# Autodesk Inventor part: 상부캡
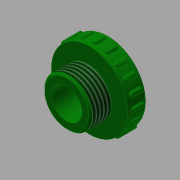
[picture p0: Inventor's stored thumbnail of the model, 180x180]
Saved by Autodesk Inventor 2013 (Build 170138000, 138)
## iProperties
Created: 2015-12
Part Number: 상부캡
Material: PC/ABS 플라스틱
Document SubType Name: Modeling
Designer: mduedu
Density: 7.86 g/cm^3
Author: mduedu
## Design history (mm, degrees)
sketch "스케치1"
  geometry: C1 r 12.5 at (0, 0); C2 r 8 at (0, 0); 1 further point
  constraints: 2 centre point, 2 coincident
  dimensions: "d1" = 25 diameter of C1; "d3" = 16 diameter of C2
extrude "돌출1" new body sketch "스케치1" distance "d4" = 12; taper "d6" = 0 deg; dims "d5" = 12, "d7" = 0
sketch "스케치2"
  geometry: C1 r 20 at (0, 0); C2 r 12.5 at (0, 0) reference; 1 further point
  constraints: 1 centre point, 1 coincident
  dimensions: "d8" = 40 diameter of C1
extrude "돌출2" join sketch "스케치2" distance "d10" = 10; taper "d11" = 0 deg
extrude "돌출3" cut sketch "스케치1" stored distance "d34" = 10; taper "d35" = 0 deg
sketch "스케치5"
  geometry: L1 (-20, 0)-(-20, 10) reference; L2 (-20, 10)-(-12.5, 10) reference; L3 (-12.5, 10)-(-12.5, 12) reference; L4 (-12.5, 12)-(12.5, 12) reference; L5 (12.5, 12)-(12.5, 10) reference; L6 (12.5, 10)-(20, 10) reference; L7 (20, 10)-(20, 0) reference; L8 (20, 0)-(12.5, 0) reference; L9 (12.5, 0)-(12.5, -12) reference; L10 (12.5, -12)-(8, -12) reference; L11 (8, -12)-(8, 0) reference; L12 (8, 0)-(-8, 0) reference; L13 (-8, 0)-(-8, -12) reference; L14 (-8, -12)-(-12.5, -12) reference; L15 (-12.5, -12)-(-12.5, 0) reference; L16 (-12.5, 0)-(-20, 0) reference; L17 (12.5, 0)-(10.5, 0); L18 (10.5, 0)-(10.5, -1); L19 (10.5, -1)-(12.5, -1); L20 (12.5, -1)-(12.5, 0); 2 further points
  constraints: 8 end point, 2 parallel, 1 horizontal, 1 midpoint, 1 perpendicular, 1 vertical alignment, 2 other
  dimensions: "d36" = 2 distance of L19.end L18.end; "d37" = 1 distance of L18.end L17.end
revolve "회전1" sketch "스케치5" stored, may be unused: angle "d38" = 90 deg
feature "스레드1" dims "d39" = 10, "d40" = 0
chamfer "모따기3" distance "d41" = 1; stored, may be unused: second distance "d42" = 2, angle "d43" = 45 deg
fillet "모깎기4" dims "d44" = 3
node "작업 평면1"
sketch "스케치7"
  geometry: L1 (1, 0)-(-1, 0); L2 (-1, 0)-(-1, 20.976); L3 (1, 20.976)-(1, 0); C1 r 20 at (0, 0) reference; A1 r 21 centre (0, 0) between (1, 20.976) and (-1, 20.976); 2 further points
  constraints: 6 end point, 2 coincident, 2 point on circle, 1 centre point, 1 horizontal, 1 midpoint, 1 parallel, 1 perpendicular
  dimensions: "d48" = 2 distance of L1.start L1.end; "d49" = 1 radial gap between concentric circles of A1 C1
extrude "돌출4" join sketch "스케치7" distance "d50" = 3; taper "d52" = 0 deg; dims "d51" = 3, "d53" = 0
fillet "모깎기5" dims "d54" = 1
fillet "모깎기6" dims "d55" = 0.5
fillet "모깎기7" dims "d59" = 1
sketch "스케치8"
  geometry: 2 further points
  constraints: 1 coincident, 1 other
feature "엠보싱1" sketch "스케치8" dims "d60" = 0.5, "d61" = 0
node "솔리드1"
pattern_circular "원형 패턴1" dims "d57" = 360 deg
node "절단 모서리 투영1"
node "절단 모서리 투영3"
